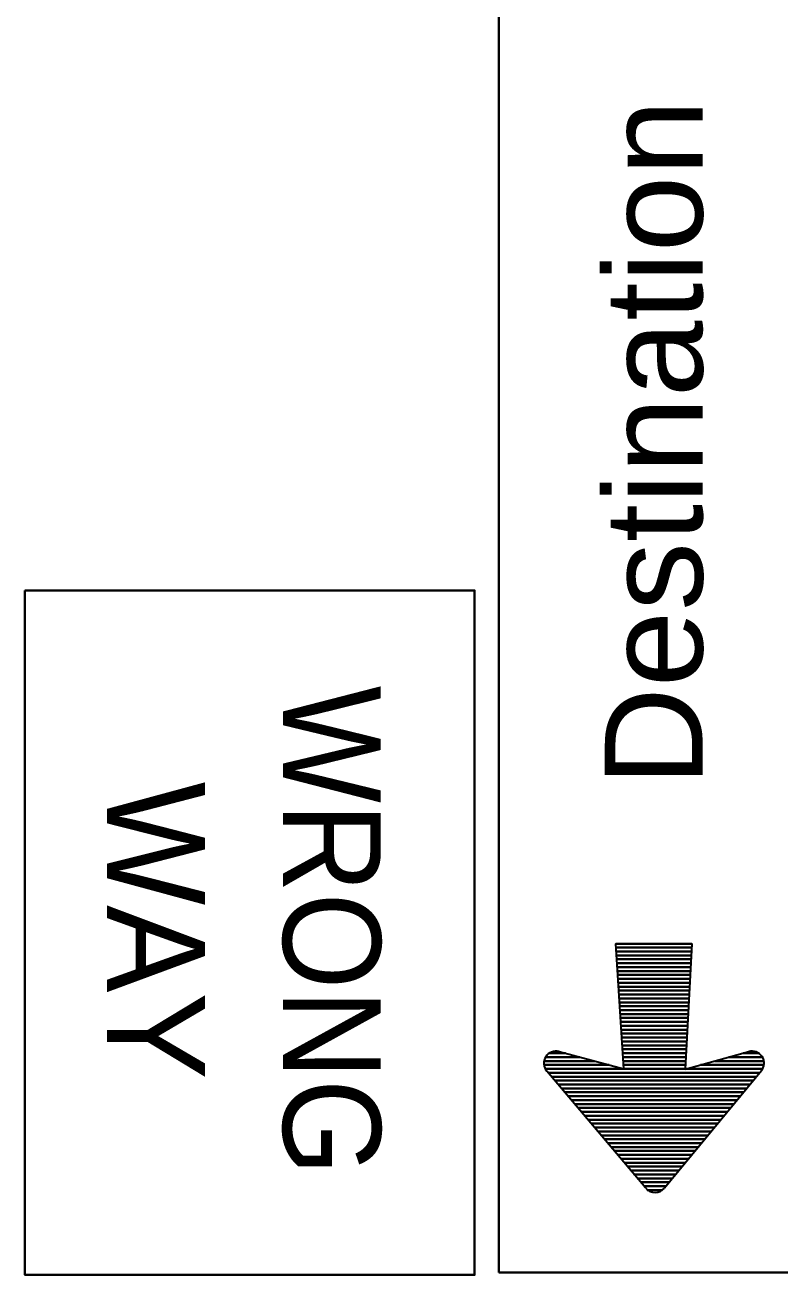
# Model space of a CAD drawing. Extents: x 1081 to 1936, y -630 to -24.
# Drawn here: x 1510 to 1533.14, y -175.76 to -137.42 of the extents above; entities that cross this region are included whole.
import ezdxf
from ezdxf.enums import TextEntityAlignment as Align

# ---------------------------------------------------------------- set-up
doc = ezdxf.new("R2010")
doc.units = 0
doc.layers.add('1', color=7, linetype='Continuous', lineweight=53)

msp = doc.modelspace()

# ---------------------------------------------------------------- linework, layer by layer
at = {"layer": '1', "lineweight": 40}
for p, q in [((1524.543, -175.686), (1524.543, -126.486)), ((1528.139, -165.598), (1530.467, -165.598)), ((1529.279, -165.598), (1530.467, -165.598)), ((1528.151, -165.718), (1530.455, -165.718)), ((1528.163, -165.838), (1530.443, -165.838)), ((1528.163, -165.958), (1530.443, -165.958)), ((1529.279, -165.718), (1530.455, -165.718)), ((1529.279, -165.838), (1530.443, -165.838)), ((1529.279, -165.958), (1530.443, -165.958)), ((1528.175, -166.078), (1530.431, -166.078)), ((1528.187, -166.198), (1530.431, -166.198)), ((1528.187, -166.318), (1530.419, -166.318)), ((1529.279, -166.078), (1530.431, -166.078)), ((1529.279, -166.198), (1530.431, -166.198)), ((1529.279, -166.318), (1530.419, -166.318)), ((1528.199, -166.438), (1530.419, -166.438)), ((1528.199, -166.558), (1530.407, -166.558)), ((1528.211, -166.678), (1530.407, -166.678)), ((1528.223, -166.798), (1530.395, -166.798)), ((1529.279, -166.438), (1530.419, -166.438)), ((1529.279, -166.558), (1530.407, -166.558)), ((1529.279, -166.678), (1530.407, -166.678)), ((1529.279, -166.798), (1530.395, -166.798)), ((1528.223, -166.918), (1530.395, -166.918)), ((1528.235, -167.038), (1530.383, -167.038)), ((1528.247, -167.158), (1530.383, -167.158)), ((1529.279, -166.918), (1530.395, -166.918)), ((1529.279, -167.038), (1530.383, -167.038)), ((1529.279, -167.158), (1530.383, -167.158)), ((1528.247, -167.278), (1530.371, -167.278)), ((1528.259, -167.398), (1530.371, -167.398)), ((1528.259, -167.518), (1530.359, -167.518)), ((1529.279, -167.278), (1530.371, -167.278)), ((1529.279, -167.398), (1530.371, -167.398)), ((1529.279, -167.518), (1530.359, -167.518)), ((1528.271, -167.638), (1530.347, -167.638)), ((1528.283, -167.758), (1530.347, -167.758)), ((1528.283, -167.878), (1530.335, -167.878)), ((1529.279, -167.638), (1530.347, -167.638)), ((1529.279, -167.758), (1530.347, -167.758)), ((1529.279, -167.878), (1530.335, -167.878)), ((1528.295, -167.998), (1530.335, -167.998)), ((1528.295, -168.118), (1530.323, -168.118)), ((1528.295, -168.238), (1530.323, -168.238)), ((1529.279, -167.998), (1530.335, -167.998)), ((1529.279, -168.118), (1530.323, -168.118)), ((1529.279, -168.238), (1530.323, -168.238)), ((1528.307, -168.358), (1530.311, -168.358)), ((1528.319, -168.478), (1530.311, -168.478)), ((1528.319, -168.598), (1530.299, -168.598)), ((1528.331, -168.718), (1530.299, -168.718)), ((1529.279, -168.358), (1530.311, -168.358)), ((1529.279, -168.478), (1530.311, -168.478)), ((1529.279, -168.598), (1530.299, -168.598)), ((1529.279, -168.718), (1530.299, -168.718)), ((1525.979, -169.078), (1527.035, -169.078)), ((1528.331, -168.838), (1530.287, -168.838)), ((1528.343, -168.958), (1530.287, -168.958)), ((1528.355, -169.078), (1530.275, -169.078)), ((1529.279, -168.838), (1530.287, -168.838)), ((1529.279, -168.958), (1530.287, -168.958)), ((1529.279, -169.078), (1530.275, -169.078)), ((1525.931, -169.318), (1527.935, -169.318)), ((1528.355, -169.198), (1530.275, -169.198)), ((1528.367, -169.318), (1530.263, -169.318)), ((1529.279, -169.198), (1530.275, -169.198)), ((1529.279, -169.318), (1530.263, -169.318)), ((1529.279, -169.438), (1530.263, -169.438)), ((1530.731, -169.318), (1532.675, -169.318)), ((1530.731, -169.318), (1532.675, -169.318)), ((1531.175, -169.198), (1532.675, -169.198)), ((1531.175, -169.198), (1532.675, -169.198)), ((1526.063, -169.558), (1532.543, -169.558)), ((1526.159, -169.678), (1532.447, -169.678)), ((1526.267, -169.798), (1532.351, -169.798)), ((1529.279, -169.558), (1532.543, -169.558)), ((1529.279, -169.678), (1532.447, -169.678)), ((1529.279, -169.798), (1532.351, -169.798)), ((1526.363, -169.918), (1532.255, -169.918)), ((1526.471, -170.038), (1532.147, -170.038)), ((1526.567, -170.158), (1532.051, -170.158)), ((1529.279, -169.918), (1532.255, -169.918)), ((1529.279, -170.038), (1532.147, -170.038)), ((1529.279, -170.158), (1532.051, -170.158)), ((1526.675, -170.278), (1531.955, -170.278)), ((1526.771, -170.398), (1531.859, -170.398)), ((1526.879, -170.518), (1531.751, -170.518)), ((1529.279, -170.278), (1531.955, -170.278)), ((1529.279, -170.398), (1531.859, -170.398)), ((1529.279, -170.518), (1531.751, -170.518)), ((1526.975, -170.638), (1531.655, -170.638)), ((1527.071, -170.758), (1531.559, -170.758)), ((1527.179, -170.878), (1531.451, -170.878)), ((1527.275, -170.998), (1531.355, -170.998)), ((1529.279, -170.638), (1531.655, -170.638)), ((1529.279, -170.758), (1531.559, -170.758)), ((1529.279, -170.878), (1531.451, -170.878)), ((1529.279, -170.998), (1531.355, -170.998)), ((1527.383, -171.118), (1531.259, -171.118)), ((1527.479, -171.238), (1531.163, -171.238)), ((1527.587, -171.358), (1531.055, -171.358)), ((1529.279, -171.118), (1531.259, -171.118)), ((1529.279, -171.238), (1531.163, -171.238)), ((1529.279, -171.358), (1531.055, -171.358)), ((1527.683, -171.478), (1530.959, -171.478)), ((1527.791, -171.598), (1530.863, -171.598)), ((1527.887, -171.718), (1530.767, -171.718)), ((1529.279, -171.478), (1530.959, -171.478)), ((1529.279, -171.598), (1530.863, -171.598)), ((1529.279, -171.718), (1530.767, -171.718)), ((1527.995, -171.838), (1530.659, -171.838)), ((1528.091, -171.958), (1530.563, -171.958)), ((1528.199, -172.078), (1530.467, -172.078)), ((1529.279, -171.838), (1530.659, -171.838)), ((1529.279, -171.958), (1530.563, -171.958)), ((1529.279, -172.078), (1530.467, -172.078)), ((1528.295, -172.198), (1530.371, -172.198)), ((1528.391, -172.318), (1530.263, -172.318)), ((1528.487, -172.438), (1530.167, -172.438)), ((1529.279, -172.198), (1530.371, -172.198)), ((1529.279, -172.318), (1530.263, -172.318)), ((1529.279, -172.438), (1530.167, -172.438)), ((1528.583, -172.558), (1530.071, -172.558)), ((1528.691, -172.678), (1529.963, -172.678)), ((1528.787, -172.798), (1529.867, -172.798)), ((1528.895, -172.918), (1529.771, -172.918)), ((1529.279, -172.558), (1530.071, -172.558)), ((1529.279, -172.678), (1529.963, -172.678)), ((1529.279, -172.798), (1529.867, -172.798)), ((1529.279, -172.918), (1529.771, -172.918)), ((1528.991, -173.038), (1529.675, -173.038)), ((1529.279, -173.038), (1529.675, -173.038)), ((1524.543, -175.686), (1534.143, -175.686))]:
    msp.add_line(p, q, dxfattribs=at)
at = {"layer": '1', "lineweight": 35}
for p, q in [((1529.051, -173.098), (1526.015, -169.51)), ((1532.603, -169.498), (1529.627, -173.098))]:
    msp.add_line(p, q, dxfattribs=at)
at = {"layer": '1', "lineweight": 40}
msp.add_lwpolyline([(1510, -154.762), (1510, -175.762), (1523.8, -175.762), (1523.8, -154.762)], close=True, dxfattribs=at)
at = {"layer": '1', "lineweight": 35}
msp.add_lwpolyline([(1526.399, -168.91), (1528.379, -169.438), (1528.139, -165.598), (1530.467, -165.598), (1530.263, -169.45), (1532.219, -168.91)], dxfattribs=at)
at = {"layer": '1', "lineweight": 40}
for points in [[(1526.087, -168.958), (1526.099, -168.958), (1526.591, -168.958)], [(1531.607, -169.078), (1532.627, -169.078), (1532.639, -169.078)], [(1531.607, -169.078), (1532.627, -169.078), (1532.639, -169.078)], [(1532.039, -168.958), (1532.519, -168.958), (1532.531, -168.958)], [(1532.039, -168.958), (1532.519, -168.958), (1532.531, -168.958)], [(1525.931, -169.198), (1525.943, -169.198), (1527.479, -169.198)], [(1525.967, -169.438), (1525.979, -169.438), (1528.379, -169.438), (1530.263, -169.438)], [(1530.299, -169.438), (1532.627, -169.438), (1532.639, -169.438)], [(1530.299, -169.438), (1532.627, -169.438), (1532.639, -169.438)], [(1529.123, -173.158), (1529.099, -173.158), (1529.123, -173.158), (1529.543, -173.158), (1529.543, -173.158)], [(1529.279, -173.158), (1529.543, -173.158), (1529.555, -173.158)]]:
    msp.add_lwpolyline(points, dxfattribs=at)
at = {"layer": '1', "lineweight": 35}
for centre, start, end in [((1526.298, -169.269), 75.1137, 220.2576), ((1532.314, -169.265), 320.43, 105.5512), ((1529.339, -172.86), 220.2565, 320.4047)]:
    msp.add_arc(centre, 0.372, start, end, dxfattribs=at)

# ---------------------------------------------------------------- texts
at = {"layer": '1'}
for s, rotation, width, p in [('Destination', 90, 1.05, (1530.797, -150.235)), ('WRONG', 270, 0.95, (1517.921, -165.2))]:
    msp.add_text(s, height=3, rotation=rotation, dxfattribs=dict(at, width=width)).set_placement(p, align=Align.CENTER)
msp.add_text('WAY', height=3, rotation=270, dxfattribs=at).set_placement((1512.521, -165.2), align=Align.CENTER)

doc.saveas('drawing.dxf')
